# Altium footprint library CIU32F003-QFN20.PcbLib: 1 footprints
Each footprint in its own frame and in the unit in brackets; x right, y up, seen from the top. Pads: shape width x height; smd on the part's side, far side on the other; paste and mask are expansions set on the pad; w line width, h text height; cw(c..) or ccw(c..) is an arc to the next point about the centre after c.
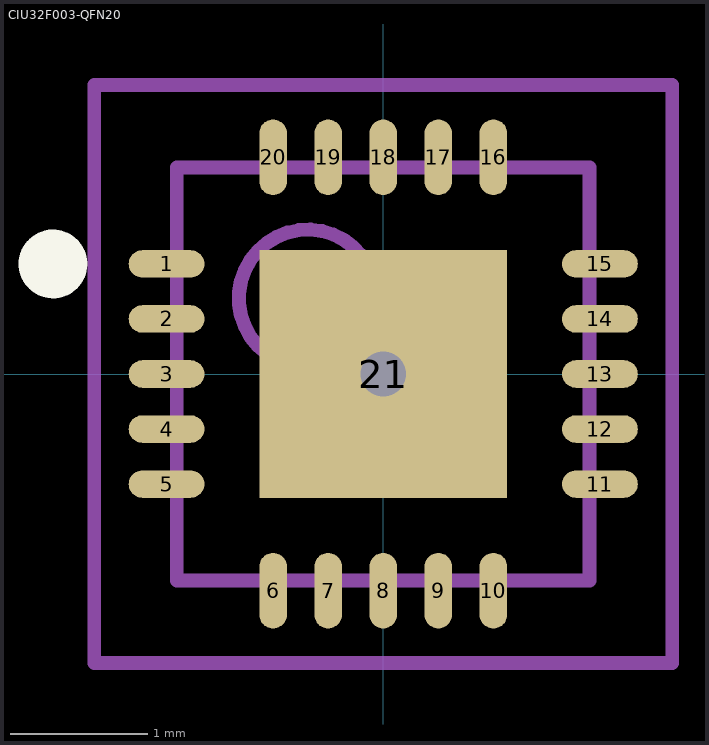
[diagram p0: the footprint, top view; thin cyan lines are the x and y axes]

## CIU32F003-QFN20 [mm] "QFN, 20-Leads, Body 3.0x3.0mm (max), Pitch 0.40mm, IPC Medium Density"
height 0.6
pads (21):
  oval 0.55x0.2 smd: 1(-1.575,0.8) 2(-1.575,0.4) 3(-1.575,0) 4(-1.575,-0.4) 5(-1.575,-0.8) 11(1.575,-0.8) 12(1.575,-0.4) 13(1.575,0) 14(1.575,0.4) 15(1.575,0.8)
  oval 0.2x0.55 smd: 6(-0.8,-1.575) 7(-0.4,-1.575) 8(0,-1.575) 9(0.4,-1.575) 10(0.8,-1.575) 16(0.8,1.575) 17(0.4,1.575) 18(0,1.575) 19(-0.4,1.575) 20(-0.8,1.575)
  rect 1.8x1.8 smd: 21(0,0)
via 0,0 diameter 0.66 hole 0.33
Top Overlay:
  circle w0.25: c-2.4,0.8 r0.125
Mechanical 13:
  circle w0.1: c-0.55,0.55 r0.5
  lines w0.1: -1.5,-1.5 -1.5,1.5 1.5,1.5 1.5,-1.5 -1.5,-1.5
Mechanical 15:
  lines w0.1: -0.5,0 0.5,0 ; 0,-0.5 0,0.5 ; -2.1,-2.1 -2.1,2.1 2.1,2.1 2.1,-2.1 -2.1,-2.1
3D body: height 0.6, standoff 0, extent -1.5,-1.5 1.5,1.5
